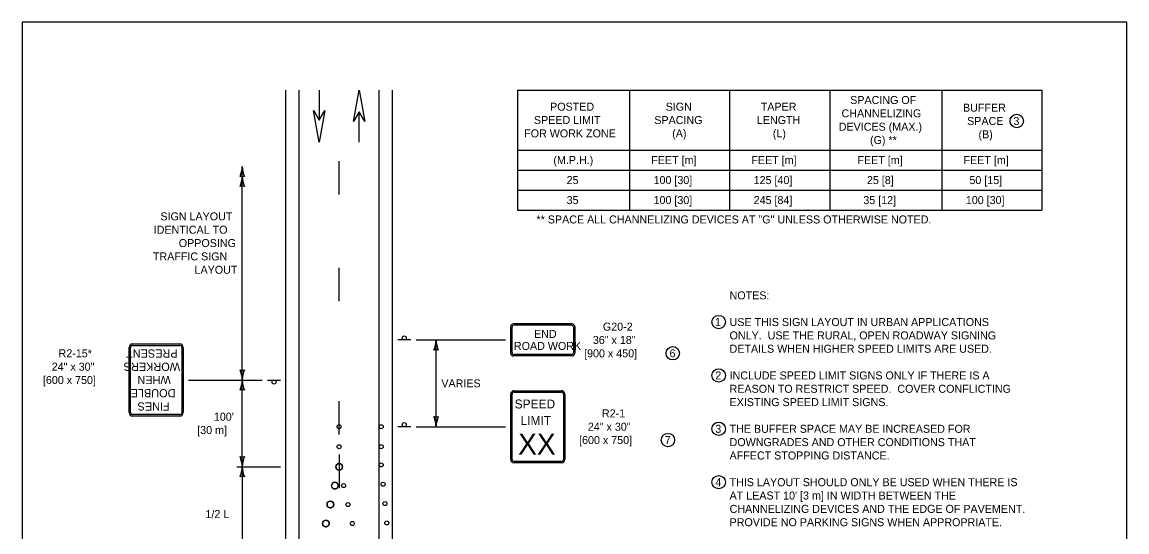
# Model space of a CAD drawing. Extents: x 49991.4 to 50021, y 49987.6 to 50011.4.
# Drawn here: x 50000.34 to 50008.61, y 50007.44 to 50011.26 of the extents above; entities that cross this region are included whole.
import ezdxf

# ---------------------------------------------------------------- set-up
doc = ezdxf.new("R2010")
doc.units = 0
for name, color, linetype in [('Level 1', 7, 'Continuous'), ('Level 2', 7, 'Continuous'), ('Level 3', 7, 'Continuous')]:
    doc.layers.add(name, color=color, linetype=linetype)

msp = doc.modelspace()

# ---------------------------------------------------------------- linework, layer by layer
at = {"layer": 'Level 1'}
for p, q in [((50002.3115, 50000.5714), (50002.3115, 50010.7538)), ((50002.4115, 50000.5714), (50002.4115, 50010.7538)), ((50002.5614, 50010.7538), (50002.5614, 50010.5279)), ((50002.5617, 50010.7538), (50002.5617, 50010.5279)), ((50003.0115, 50000.5714), (50003.0115, 50010.7538)), ((50003.1115, 50000.5714), (50003.1115, 50010.7538)), ((50002.8611, 50010.3637), (50002.8611, 50010.5896)), ((50002.8614, 50010.3637), (50002.8614, 50010.5896)), ((50002.7115, 50009.9716), (50002.7115, 50010.2216)), ((50002.7115, 50009.1716), (50002.7115, 50009.4216)), ((50003.9971, 50008.7805), (50003.9971, 50008.9805)), ((50004.0071, 50008.7855), (50004.0071, 50008.9755)), ((50004.4571, 50009.0005), (50004.0171, 50009.0005)), ((50004.4521, 50008.9905), (50004.0221, 50008.9905)), ((50004.4671, 50008.9755), (50004.4671, 50008.7855)), ((50004.4771, 50008.9805), (50004.4771, 50008.7805)), ((50001.1381, 50008.3358), (50001.1381, 50008.8252)), ((50001.1486, 50008.3358), (50001.1486, 50008.8252)), ((50001.1634, 50008.8506), (50001.5178, 50008.8506)), ((50001.1634, 50008.84), (50001.5178, 50008.84)), ((50001.5326, 50008.8252), (50001.5326, 50008.3358)), ((50001.5431, 50008.8252), (50001.5431, 50008.3358)), ((50003.2475, 50008.8805), (50003.1515, 50008.8805)), ((50004.457, 50008.7605), (50004.017, 50008.7605)), ((50004.4521, 50008.7705), (50004.0221, 50008.7705)), ((50002.1755, 50008.5805), (50002.2715, 50008.5805)), ((50003.9971, 50007.9858), (50003.9971, 50008.4752)), ((50004.0077, 50007.9858), (50004.0077, 50008.4752)), ((50004.0224, 50008.5006), (50004.3769, 50008.5006)), ((50004.0224, 50008.49), (50004.3769, 50008.49)), ((50004.1996, 50008.5006), (50004.1996, 50008.5006)), ((50004.3916, 50008.4752), (50004.3916, 50007.9858)), ((50004.4022, 50008.4752), (50004.4022, 50007.9858)), ((50002.7115, 50008.1716), (50002.7115, 50008.4216)), ((50001.5178, 50008.321), (50001.1634, 50008.321)), ((50001.5178, 50008.3105), (50001.1634, 50008.3105)), ((50001.3406, 50008.3105), (50001.3406, 50008.3105)), ((50003.2475, 50008.2305), (50003.1515, 50008.2305)), ((50002.7115, 50008.0211), (50002.7115, 50007.7711)), ((50004.3769, 50007.971), (50004.0224, 50007.971)), ((50004.3769, 50007.9605), (50004.0224, 50007.9605))]:
    msp.add_line(p, q, dxfattribs=at)
for points in [[(50008.6146, 50011.2628), (50000.3356, 50011.2628), (50000.3356, 50000.0624), (50008.6146, 50000.0624)], [(50002.8194, 50010.5173), (50002.8611, 50010.7538), (50002.903, 50010.5173), (50002.8611, 50010.5895)], [(50002.6034, 50010.6002), (50002.5617, 50010.3637), (50002.5198, 50010.6002), (50002.5617, 50010.528)]]:
    msp.add_lwpolyline(points, close=True, dxfattribs=at)
for centre, radius in [((50003.1995, 50008.8958), 0.0152), ((50002.2235, 50008.5653), 0.0152), ((50002.7115, 50008.2305), 0.015), ((50003.0266, 50008.2305), 0.015), ((50003.1995, 50008.2458), 0.0152), ((50002.7115, 50008.0805), 0.015), ((50003.0266, 50008.0805), 0.015), ((50002.7116, 50007.9305), 0.025), ((50003.0266, 50007.9442), 0.015), ((50002.6786, 50007.7887), 0.025), ((50003.0406, 50007.7992), 0.015), ((50003.0406, 50007.7992), 0.015), ((50002.7446, 50007.7887), 0.015), ((50002.6456, 50007.6469), 0.025), ((50002.7776, 50007.6469), 0.015), ((50002.7776, 50007.6469), 0.015), ((50003.0545, 50007.6542), 0.015), ((50002.6126, 50007.505), 0.025), ((50002.8106, 50007.5051), 0.015), ((50002.8106, 50007.5051), 0.015), ((50003.0685, 50007.5093), 0.015)]:
    msp.add_circle(centre, radius, dxfattribs=at)
for centre, radius, start, end in [((50004.0171, 50008.9805), 0.02, 90, 180), ((50004.0221, 50008.9755), 0.015, 90, 180), ((50004.4521, 50008.9755), 0.015, 360, 90), ((50004.4571, 50008.9805), 0.02, 360, 90), ((50001.1634, 50008.8252), 0.0253, 90, 180), ((50001.1634, 50008.8252), 0.0148, 90, 180), ((50001.5178, 50008.8252), 0.0253, 360, 90), ((50001.5178, 50008.8252), 0.0148, 360, 90), ((50004.017, 50008.7805), 0.02, 180, 270), ((50004.0221, 50008.7855), 0.015, 180, 270), ((50004.4521, 50008.7855), 0.015, 270, 360), ((50004.457, 50008.7805), 0.02, 270, 360), ((50004.0224, 50008.4752), 0.0253, 90, 180), ((50004.0224, 50008.4752), 0.0148, 90, 180), ((50004.3769, 50008.4752), 0.0253, 0, 90), ((50004.3769, 50008.4752), 0.0148, 0, 90), ((50001.1634, 50008.3358), 0.0253, 180, 270), ((50001.1634, 50008.3358), 0.0148, 180, 270), ((50001.5178, 50008.3358), 0.0148, 270, 360), ((50001.5178, 50008.3358), 0.0253, 270, 360), ((50004.0224, 50007.9858), 0.0253, 180, 270), ((50004.0224, 50007.9858), 0.0148, 180, 270), ((50004.3769, 50007.9858), 0.0148, 270, 360), ((50004.3769, 50007.9858), 0.0253, 270, 360), ((50002.7116, 50007.9305), 0.025, 21.40137, 201.40137), ((50002.7116, 50007.9305), 0.025, 201.40137, 21.40137), ((50002.6786, 50007.7887), 0.025, 21.40137, 201.40137), ((50002.6786, 50007.7887), 0.025, 201.40137, 21.40137), ((50002.6456, 50007.6469), 0.025, 21.40137, 201.40137), ((50002.6456, 50007.6469), 0.025, 201.40137, 21.40137), ((50002.6126, 50007.505), 0.025, 21.40137, 201.40137), ((50002.6126, 50007.505), 0.025, 201.40137, 21.40137)]:
    msp.add_arc(centre, radius, start, end, dxfattribs=at)
at = {"layer": 'Level 2'}
for p, q in [((50004.0477, 50010.7538), (50007.9777, 50010.7538)), ((50004.0477, 50010.7538), (50004.0477, 50009.8538)), ((50004.8877, 50010.7538), (50004.8877, 50009.8538)), ((50005.6377, 50010.7538), (50005.6377, 50009.8538)), ((50006.3877, 50010.7538), (50006.3877, 50009.8538)), ((50007.2277, 50010.7538), (50007.2277, 50009.8538)), ((50007.9777, 50010.7538), (50007.9777, 50009.8538)), ((50004.0477, 50010.3038), (50007.9777, 50010.3038)), ((50004.0477, 50010.1538), (50007.9777, 50010.1538)), ((50004.0477, 50010.0038), (50007.9777, 50010.0038)), ((50004.0477, 50009.8538), (50007.9777, 50009.8538))]:
    msp.add_line(p, q, dxfattribs=at)
for centre in [(50007.7892, 50010.5215), (50005.5555, 50009.0149), (50005.2118, 50008.7806), (50005.5555, 50008.6149), (50005.5555, 50008.2149), (50005.1753, 50008.1306), (50005.5555, 50007.8149)]:
    msp.add_circle(centre, 0.0501, dxfattribs=at)
at = {"layer": 'Level 3'}
for p, q in [((50001.9855, 50008.5805), (50001.9855, 50010.1805)), ((50003.2875, 50008.8805), (50003.9571, 50008.8805)), ((50003.4375, 50008.2305), (50003.4375, 50008.8805)), ((50001.5831, 50008.5805), (50002.1355, 50008.5805)), ((50001.9855, 50007.9305), (50001.9855, 50008.5805)), ((50003.2875, 50008.2305), (50003.9571, 50008.2305)), ((50001.9455, 50007.9305), (50002.2715, 50007.9305)), ((50001.9855, 50007.9305), (50001.9855, 50007.2214))]:
    msp.add_line(p, q, dxfattribs=at)
for centre, radius, start, end in [((50001.7634, 50010.1897), 0.2223, 337.45601, 357.63952), ((50002.2182, 50010.192), 0.233, 182.82731, 202.07716), ((50001.9855, 50010.0523), 0.0548, 72.13882, 107.86118), ((50001.7634, 50010.1162), 0.2223, 337.45601, 357.63952), ((50002.2182, 50010.1186), 0.233, 182.82731, 202.07716), ((50001.9855, 50009.9789), 0.0548, 72.13882, 107.86118), ((50003.2154, 50008.8897), 0.2223, 337.45601, 357.63952), ((50003.4375, 50008.7523), 0.0548, 72.13882, 107.86118), ((50003.6702, 50008.892), 0.233, 182.82731, 202.07716), ((50001.9855, 50008.7087), 0.0548, 252.13882, 287.86118), ((50001.7528, 50008.569), 0.233, 2.82731, 22.07716), ((50002.2076, 50008.5714), 0.2223, 157.45601, 177.63952), ((50001.7634, 50008.5897), 0.2223, 337.45601, 357.63952), ((50002.2182, 50008.592), 0.233, 182.82731, 202.07716), ((50001.9855, 50008.4523), 0.0548, 72.13882, 107.86118), ((50003.4375, 50008.3587), 0.0548, 252.13882, 287.86118), ((50003.2048, 50008.219), 0.233, 2.82731, 22.07716), ((50003.6596, 50008.2214), 0.2223, 157.45601, 177.63952), ((50001.9855, 50008.0587), 0.0548, 252.13882, 287.86118), ((50001.7528, 50007.919), 0.233, 2.82731, 22.07716), ((50002.2076, 50007.9214), 0.2223, 157.45601, 177.63952), ((50001.7634, 50007.9397), 0.2223, 337.45601, 357.63952), ((50002.2182, 50007.942), 0.233, 182.82731, 202.07716), ((50001.9855, 50007.8023), 0.0548, 72.13882, 107.86118)]:
    msp.add_arc(centre, radius, start, end, dxfattribs=at)

# ---------------------------------------------------------------- texts
at = {"layer": 'Level 1'}
for s, height, rotation, p in [('END', 0.06, 360, (50004.1719, 50008.8959)), ('PRESENT', 0.06118, 180, (50001.5011, 50008.8094)), ('ROAD WORK', 0.06, 360, (50004.0212, 50008.8059)), ('WORKERS', 0.06118, 180, (50001.5192, 50008.7103)), ('WHEN', 0.06118, 180, (50001.4497, 50008.6111)), ('DOUBLE', 0.06118, 180, (50001.4852, 50008.512)), ('FINES', 0.06118, 180, (50001.4417, 50008.4128))]:
    msp.add_text(s, height=height, rotation=rotation, dxfattribs=at).set_placement(p)
for s, height, p in [('SPEED', 0.06695, (50004.0266, 50008.3673)), ('LIMIT', 0.06695, (50004.0709, 50008.2435)), ('XX', 0.15772, (50004.0526, 50008.0216))]:
    msp.add_text(s, height=height, dxfattribs=at).set_placement(p)
at = {"layer": 'Level 2'}
for s, p in [('SPACING OF', (50006.5411, 50010.6488)), ('POSTED', (50004.2923, 50010.5988)), ('SIGN', (50005.1583, 50010.5988)), ('TAPER', (50005.8709, 50010.5988)), ('BUFFER', (50007.3866, 50010.5915)), ('SPEED LIMIT', (50004.171, 50010.4988)), ('SPACING', (50005.0732, 50010.4988)), ('LENGTH', (50005.8418, 50010.4988)), ('CHANNELIZING', (50006.4764, 50010.5488)), ('SPACE', (50007.4174, 50010.4915)), ('3', (50007.7642, 50010.4916)), ('FOR WORK ZONE', (50004.0981, 50010.3988)), ('(A)', (50005.2073, 50010.3988)), ('(L)', (50005.961, 50010.3988)), ('DEVICES (MAX.)', (50006.455, 50010.4488)), ('(G) **', (50006.6897, 50010.3488)), ('(B)', (50007.5025, 50010.3915)), ('(M.P.H.)', (50004.317, 50010.1988)), ('FEET [m]', (50005.0504, 50010.1988)), ('FEET [m]', (50005.8004, 50010.1988)), ('FEET [m]', (50006.5954, 50010.1988)), ('FEET [m]', (50007.3904, 50010.1988)), ('25', (50004.4158, 50010.0488)), ('100 [30]', (50005.0675, 50010.0488)), ('125 [40]', (50005.8175, 50010.0488)), ('25 [8]', (50006.6664, 50010.0488)), ('50 [15]', (50007.4345, 50010.0488)), ('100 [30]', (50005.0675, 50009.8988)), ('245 [84]', (50005.8175, 50009.8988)), ('35 [12]', (50006.6395, 50009.8988)), ('100 [30]', (50007.4075, 50009.8988)), ('35', (50004.4159, 50009.8988)), ('** SPACE ALL CHANNELIZING DEVICES AT "G" UNLESS OTHERWISE NOTED.', (50004.1904, 50009.7538))]:
    msp.add_text(s, height=0.06, rotation=360, dxfattribs=at).set_placement(p)
for s, p in [('SIGN LAYOUT', (50001.372, 50009.7768)), ('IDENTICAL TO', (50001.3218, 50009.6768)), ('OPPOSING', (50001.5099, 50009.5768)), ('TRAFFIC SIGN', (50001.3159, 50009.4768)), ('LAYOUT', (50001.628, 50009.3768)), ('NOTES:', (50005.6372, 50009.1848)), ('G20-2', (50004.6878, 50008.9505)), ('1', (50005.5278, 50008.9848)), ('USE THIS SIGN LAYOUT IN URBAN APPLICATIONS', (50005.6372, 50008.9848)), ('36" x 18"', (50004.6126, 50008.8505)), ('ONLY.  USE THE RURAL, OPEN ROADWAY SIGNING', (50005.6372, 50008.8848)), ('R2-15*', (50000.6089, 50008.7505)), ('[900 x 450]', (50004.547, 50008.7505)), ('6', (50005.1873, 50008.7506)), ('DETAILS WHEN HIGHER SPEED LIMITS ARE USED.', (50005.6372, 50008.7848)), ('24" x 30"', (50000.5574, 50008.6505)), ('2', (50005.5303, 50008.5849)), ('INCLUDE SPEED LIMIT SIGNS ONLY IF THERE IS A', (50005.6372, 50008.5848)), ('[600 x 750]', (50000.4918, 50008.5505)), ('VARIES', (50003.4775, 50008.5255)), ('REASON TO RESTRICT SPEED.  COVER CONFLICTING', (50005.6372, 50008.4848)), ('EXISTING SPEED LIMIT SIGNS.', (50005.6372, 50008.3848)), ("100'", (50001.7727, 50008.2755)), ('R2-1', (50004.6806, 50008.3005)), ('[30 m]', (50001.6478, 50008.1755)), ('24" x 30"', (50004.5751, 50008.2005)), ('3', (50005.5303, 50008.1849)), ('THE BUFFER SPACE MAY BE INCREASED FOR', (50005.6372, 50008.1848)), ('[600 x 750]', (50004.5095, 50008.1005)), ('7', (50005.1515, 50008.1006)), ('DOWNGRADES AND OTHER CONDITIONS THAT', (50005.6372, 50008.0848)), ('AFFECT STOPPING DISTANCE.', (50005.6372, 50007.9848)), ('4', (50005.5303, 50007.7849)), ('THIS LAYOUT SHOULD ONLY BE USED WHEN THERE IS', (50005.6372, 50007.7848)), ("AT LEAST 10' [3 m] IN WIDTH BETWEEN THE ", (50005.6372, 50007.6848)), ('CHANNELIZING DEVICES AND THE EDGE OF PAVEMENT. ', (50005.6372, 50007.5848)), ('1/2 L', (50001.7097, 50007.5459)), ('PROVIDE NO PARKING SIGNS WHEN APPROPRIATE.', (50005.6372, 50007.4848))]:
    msp.add_text(s, height=0.06, dxfattribs=at).set_placement(p)

doc.saveas('drawing.dxf')
